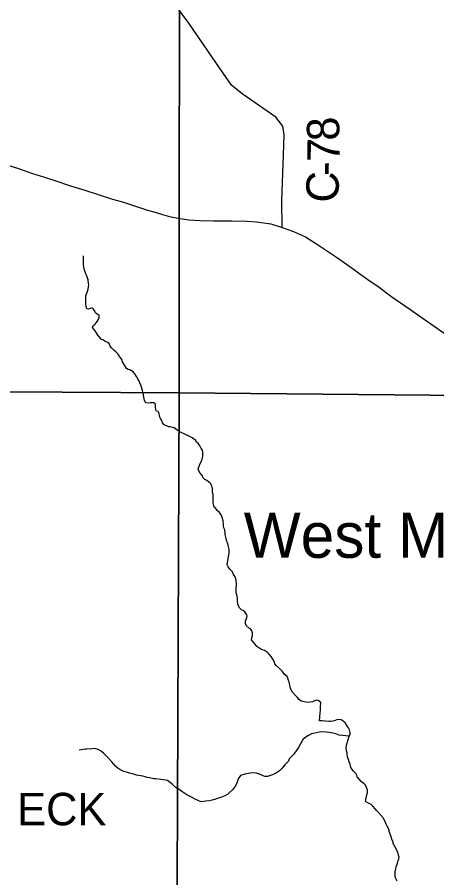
# Model space of a CAD drawing. Extents: x 0 to 34, y 0 to 22.
# Drawn here: x 3.881 to 4.616, y 17.286 to 18.793 of the extents above; entities that cross this region are included whole.
import ezdxf

# ---------------------------------------------------------------- set-up
doc = ezdxf.new("R2010")
doc.units = 0
for name, color, linetype in [('GM_X_Corporation', 7, 'Continuous'), ('GM_X_County_Road', 7, 'Continuous'), ('GM_X_County_Road_Text', 7, 'Continuous'), ('GM_X_Minor_River', 7, 'Continuous'), ('GM_X_State_Route', 7, 'Continuous'), ('GM_X_Township_Road_Text', 7, 'Continuous'), ('GM_X_Unincorporated_Text', 7, 'Continuous')]:
    doc.layers.add(name, color=color, linetype=linetype)

msp = doc.modelspace()

# ---------------------------------------------------------------- linework, layer by layer
at = {"layer": 'GM_X_Corporation'}
for points in [[(4.1654, 19.1412), (4.1647, 18.1352), (3.1398, 18.1413), (3.1497, 19.1471)], [(4.1654, 19.1412), (5.1759, 19.1377), (5.169, 18.1258), (4.1647, 18.1352)], [(4.1647, 18.1352), (4.1603, 17.1368), (3.1266, 17.137), (3.1398, 18.1413)], [(4.1647, 18.1352), (5.169, 18.1258), (5.1609, 17.1336), (4.1603, 17.1368)]]:
    msp.add_lwpolyline(points, close=True, dxfattribs=at)
at = {"layer": 'GM_X_County_Road'}
msp.add_lwpolyline([(4.3449, 18.425), (4.3444, 18.4716), (4.3475, 18.5521), (4.3483, 18.5869), (4.346, 18.602), (4.3336, 18.6179), (4.2747, 18.6589), (4.2565, 18.674), (4.2414, 18.6953), (4.1814, 18.7824), (4.0847, 18.9132), (3.901, 19.1674), (3.8689, 19.2091)], dxfattribs=at)
at = {"layer": 'GM_X_Minor_River'}
for points in [[(3.9973, 18.3603), (3.9973, 18.363), (3.997, 18.3668), (3.997, 18.3755)], [(4.2056, 18.0349), (4.2033, 18.0376), (4.2007, 18.0426), (4.1985, 18.046), (4.1947, 18.0491), (4.1936, 18.0517), (4.1876, 18.0567), (4.1834, 18.059), (4.1793, 18.0606), (4.1733, 18.0637), (4.1684, 18.066), (4.1638, 18.0683), (4.1612, 18.0698), (4.1559, 18.0741), (4.1529, 18.0748), (4.1491, 18.0756), (4.1465, 18.076), (4.1435, 18.0768), (4.1382, 18.0792), (4.1356, 18.0826), (4.1348, 18.0853), (4.1319, 18.0902), (4.1307, 18.0929), (4.13, 18.0955), (4.1297, 18.099), (4.1278, 18.1024), (4.1251, 18.1032), (4.1237, 18.1058), (4.1229, 18.1108), (4.123, 18.1153), (4.1207, 18.118), (4.1173, 18.1177), (4.1147, 18.1177), (4.1101, 18.1173), (4.1063, 18.1178), (4.1037, 18.122), (4.1034, 18.125), (4.1015, 18.1345), (4.1004, 18.1394), (4.0993, 18.1436), (4.0975, 18.1489), (4.0938, 18.1569), (4.0923, 18.16), (4.09, 18.1642), (4.087, 18.1684), (4.084, 18.1722), (4.0814, 18.1737), (4.078, 18.1757), (4.0754, 18.1764), (4.0724, 18.178), (4.0705, 18.1807), (4.0653, 18.1898), (4.0645, 18.1936), (4.0608, 18.1982), (4.0578, 18.2028), (4.0537, 18.207), (4.0507, 18.2097), (4.0462, 18.2143), (4.0439, 18.2173), (4.0424, 18.2204), (4.0402, 18.2234), (4.0353, 18.2254), (4.0319, 18.2273), (4.0281, 18.2292), (4.0255, 18.2323), (4.0225, 18.2365), (4.0206, 18.2391), (4.0176, 18.2437), (4.0146, 18.2472), (4.0131, 18.2502), (4.0139, 18.2532), (4.0173, 18.2555), (4.0212, 18.26), (4.0227, 18.263), (4.0246, 18.2672), (4.0243, 18.271), (4.0209, 18.2729), (4.0182, 18.2752), (4.0168, 18.2786), (4.0149, 18.2821), (4.0123, 18.2844), (4.0092, 18.2832), (4.0054, 18.2821), (4.0028, 18.2822), (4.0017, 18.2867), (4.0013, 18.2898), (4.001, 18.2943), (4.0011, 18.3053), (4.0034, 18.3114), (4.0053, 18.317), (4.0057, 18.3212), (4.0065, 18.3242), (4.0061, 18.3269), (4.0054, 18.333), (4.0036, 18.3387), (4.0025, 18.3413), (4.001, 18.344), (3.9999, 18.347), (3.9984, 18.352), (3.9977, 18.3562), (3.9973, 18.3603)], [(4.3569, 17.6293), (4.3562, 17.6319), (4.3547, 17.6357), (4.3539, 17.6384), (4.3487, 17.6426), (4.3453, 17.6472), (4.3401, 17.6529), (4.3344, 17.6579), (4.3322, 17.661), (4.3314, 17.664), (4.3288, 17.669), (4.3255, 17.6735), (4.3217, 17.6781), (4.3195, 17.6808), (4.3138, 17.6839), (4.31, 17.6854), (4.3074, 17.6866), (4.3006, 17.6912), (4.2976, 17.6954), (4.2939, 17.6992), (4.2913, 17.7031), (4.2917, 17.7061), (4.2928, 17.7102), (4.2932, 17.7144), (4.2918, 17.7186), (4.2903, 17.7216), (4.2876, 17.7224), (4.282, 17.7282), (4.2809, 17.7316), (4.2809, 17.7354), (4.2828, 17.7418), (4.2836, 17.7448), (4.2821, 17.7486), (4.2795, 17.7517), (4.2769, 17.754), (4.2735, 17.7556), (4.2701, 17.7586), (4.2675, 17.7655), (4.2668, 17.7719), (4.2665, 17.7761), (4.2654, 17.7818), (4.2643, 17.7852), (4.2643, 17.7932), (4.2647, 17.7973), (4.2647, 17.8004), (4.2644, 17.8065), (4.2637, 17.8095), (4.2629, 17.8129), (4.26, 17.8171), (4.2577, 17.8217), (4.2536, 17.8263), (4.2502, 17.8305), (4.2484, 17.8339), (4.2499, 17.8419), (4.2511, 17.8479), (4.2515, 17.8506), (4.2523, 17.8555), (4.2523, 17.8616), (4.2512, 17.8661), (4.2505, 17.8688), (4.249, 17.8726), (4.2479, 17.8753), (4.2468, 17.8802), (4.2453, 17.887), (4.245, 17.8901), (4.2443, 17.8954), (4.2428, 17.8992), (4.2424, 17.9018), (4.2421, 17.9053), (4.2414, 17.911), (4.2402, 17.9151), (4.2395, 17.9186), (4.238, 17.922), (4.235, 17.9258), (4.2313, 17.9296), (4.2287, 17.9331), (4.226, 17.9354), (4.2242, 17.9434), (4.2242, 17.9464), (4.2239, 17.954), (4.2239, 17.9574), (4.2232, 17.9608), (4.2228, 17.9635), (4.2229, 17.9676), (4.2221, 17.9707), (4.2214, 17.9733), (4.2199, 17.976), (4.2161, 17.9795), (4.2128, 17.9818), (4.2097, 17.9833), (4.206, 17.9871), (4.2052, 17.9898), (4.2011, 17.9948), (4.1993, 17.999), (4.1978, 18.0024), (4.2016, 18.0114), (4.2043, 18.0167), (4.2047, 18.0194), (4.2063, 18.0247), (4.2063, 18.0315), (4.2056, 18.0349)], [(4.5465, 17.2805), (4.5435, 17.2862), (4.5427, 17.2889), (4.5428, 17.2965), (4.5432, 17.2995), (4.544, 17.3021), (4.5444, 17.3052), (4.5471, 17.3116), (4.5479, 17.3165), (4.5494, 17.3192), (4.5498, 17.3218), (4.5487, 17.326), (4.5476, 17.3313), (4.542, 17.3408), (4.5394, 17.3462), (4.539, 17.3488), (4.5372, 17.3538), (4.5353, 17.3595), (4.5324, 17.3675), (4.532, 17.3701), (4.529, 17.3766), (4.5268, 17.38), (4.5253, 17.3846), (4.5216, 17.3911), (4.5129, 17.401), (4.5099, 17.4041), (4.5077, 17.4068), (4.5036, 17.4114), (4.5006, 17.4144), (4.4949, 17.4175), (4.4911, 17.4198), (4.4919, 17.4259), (4.4931, 17.4312), (4.4943, 17.4353), (4.4943, 17.4399), (4.4928, 17.4441), (4.4906, 17.4483), (4.4887, 17.4509), (4.4831, 17.4548), (4.4763, 17.4628), (4.4752, 17.4674), (4.47, 17.4731), (4.4659, 17.4784), (4.4647, 17.4819), (4.464, 17.4849), (4.4625, 17.4895), (4.461, 17.4933), (4.4599, 17.4963), (4.4588, 17.502), (4.4589, 17.5047), (4.4577, 17.5085), (4.4567, 17.5134), (4.4578, 17.5183), (4.4594, 17.524), (4.4605, 17.5286), (4.4621, 17.5339), (4.464, 17.5372), (4.4637, 17.5407), (4.4629, 17.5452), (4.4611, 17.5487), (4.4592, 17.5513), (4.4558, 17.5567), (4.4517, 17.5605), (4.4483, 17.5628), (4.4438, 17.5632), (4.4404, 17.5625), (4.4377, 17.5614), (4.4339, 17.5603), (4.4298, 17.5599), (4.4264, 17.56), (4.415, 17.5608), (4.4101, 17.5613), (4.4109, 17.5677), (4.4117, 17.5757), (4.4118, 17.5791), (4.4122, 17.5848), (4.4122, 17.5878), (4.4126, 17.5904), (4.4126, 17.5931), (4.4081, 17.5965), (4.4047, 17.597), (4.3979, 17.594), (4.3937, 17.5936), (4.3907, 17.5933), (4.3835, 17.5945), (4.3786, 17.5957), (4.3741, 17.5984), (4.3715, 17.6018), (4.3677, 17.606), (4.3632, 17.611), (4.3598, 17.6175), (4.3587, 17.6205), (4.3584, 17.6236), (4.3569, 17.6293)], [(4.4621, 17.5339), (4.4447, 17.5359), (4.4387, 17.5382), (4.4334, 17.5394), (4.4277, 17.5406), (4.4224, 17.5414), (4.4126, 17.5415), (4.4024, 17.5397), (4.3963, 17.5383), (4.391, 17.5356), (4.3861, 17.5327), (4.3819, 17.5289), (4.3769, 17.521), (4.3735, 17.5146), (4.3696, 17.5085), (4.365, 17.5021), (4.357, 17.4942), (4.3563, 17.4905), (4.3498, 17.4837), (4.3452, 17.478), (4.3403, 17.4735), (4.333, 17.4687), (4.3281, 17.4665), (4.3247, 17.465), (4.3194, 17.4635), (4.3148, 17.4635), (4.3115, 17.4647), (4.3081, 17.4663), (4.3035, 17.4682), (4.3001, 17.4694), (4.2933, 17.4702), (4.2888, 17.4695), (4.2831, 17.468), (4.2793, 17.4677), (4.2721, 17.4651), (4.2679, 17.4594), (4.266, 17.4534), (4.2637, 17.4485), (4.2614, 17.4447), (4.2583, 17.4405), (4.253, 17.4353), (4.2492, 17.4319), (4.2446, 17.4297), (4.2389, 17.4271), (4.2355, 17.426), (4.2283, 17.4238), (4.2226, 17.4219), (4.2173, 17.4212), (4.2113, 17.4201), (4.2033, 17.4194), (4.1939, 17.4233), (4.1852, 17.4279), (4.1781, 17.4314), (4.1691, 17.4372), (4.1645, 17.4407), (4.1585, 17.4445), (4.1525, 17.4499), (4.1491, 17.4529), (4.1442, 17.4568), (4.1408, 17.4572), (4.1325, 17.4584), (4.1238, 17.4592), (4.1204, 17.4596), (4.1125, 17.4612), (4.1083, 17.4617), (4.1049, 17.4628), (4.1012, 17.464), (4.094, 17.4652), (4.0898, 17.466), (4.0846, 17.4676), (4.0778, 17.4695), (4.0725, 17.4711), (4.068, 17.4723), (4.0608, 17.4757), (4.0574, 17.478), (4.0537, 17.4811), (4.0499, 17.4857), (4.0465, 17.4895), (4.0401, 17.496), (4.0368, 17.4999), (4.033, 17.5041), (4.0278, 17.5079), (4.0229, 17.5106), (4.0168, 17.5126), (4.0115, 17.5122), (4.0032, 17.5115), (3.9998, 17.5112), (3.9896, 17.5094)]]:
    msp.add_lwpolyline(points, dxfattribs=at)
at = {"layer": 'GM_X_State_Route'}
for points in [[(3.8543, 18.5373), (3.8866, 18.5267), (3.9061, 18.52), (3.9289, 18.5132), (3.947, 18.5072), (3.9742, 18.498), (3.9996, 18.4901), (4.0227, 18.4824), (4.048, 18.4746), (4.0669, 18.469), (4.0845, 18.4633), (4.0986, 18.4585), (4.1092, 18.4552), (4.1226, 18.4516), (4.1356, 18.4475), (4.1477, 18.4444), (4.1628, 18.4409), (4.1816, 18.4384), (4.2016, 18.437), (4.2249, 18.4363), (4.2305, 18.4363)], [(4.2305, 18.4363), (4.2568, 18.4365), (4.2832, 18.4357), (4.3001, 18.4345), (4.325, 18.4314), (4.3449, 18.425)], [(4.3449, 18.425), (4.3649, 18.418), (4.3856, 18.4085), (4.4088, 18.3939), (4.4399, 18.3729), (4.4631, 18.3563), (4.4829, 18.3425), (4.495, 18.3339), (4.5131, 18.3215), (4.5367, 18.3036), (4.5682, 18.2821), (4.6285, 18.2397)]]:
    msp.add_lwpolyline(points, dxfattribs=at)

# ---------------------------------------------------------------- texts
at = {"layer": 'GM_X_County_Road_Text'}
for s, rotation, p in [('8', 92.9016, (4.446, 18.5778)), ('7', 88.9116, (4.4454, 18.5385)), ('-', 88.175, (4.4447, 18.5144)), ('C', 87.9876, (4.443, 18.4676))]:
    msp.add_text(s, height=0.0568, rotation=rotation, dxfattribs=at).set_placement(p)
at = {"layer": 'GM_X_Township_Road_Text'}
msp.add_text('ECK', height=0.05682, rotation=0, dxfattribs=at).set_placement((3.881, 17.3781))
at = {"layer": 'GM_X_Unincorporated_Text'}
msp.add_text('West Middletown', height=0.078977, rotation=0, dxfattribs=at).set_placement((4.2777, 17.8465))

doc.saveas('drawing.dxf')
